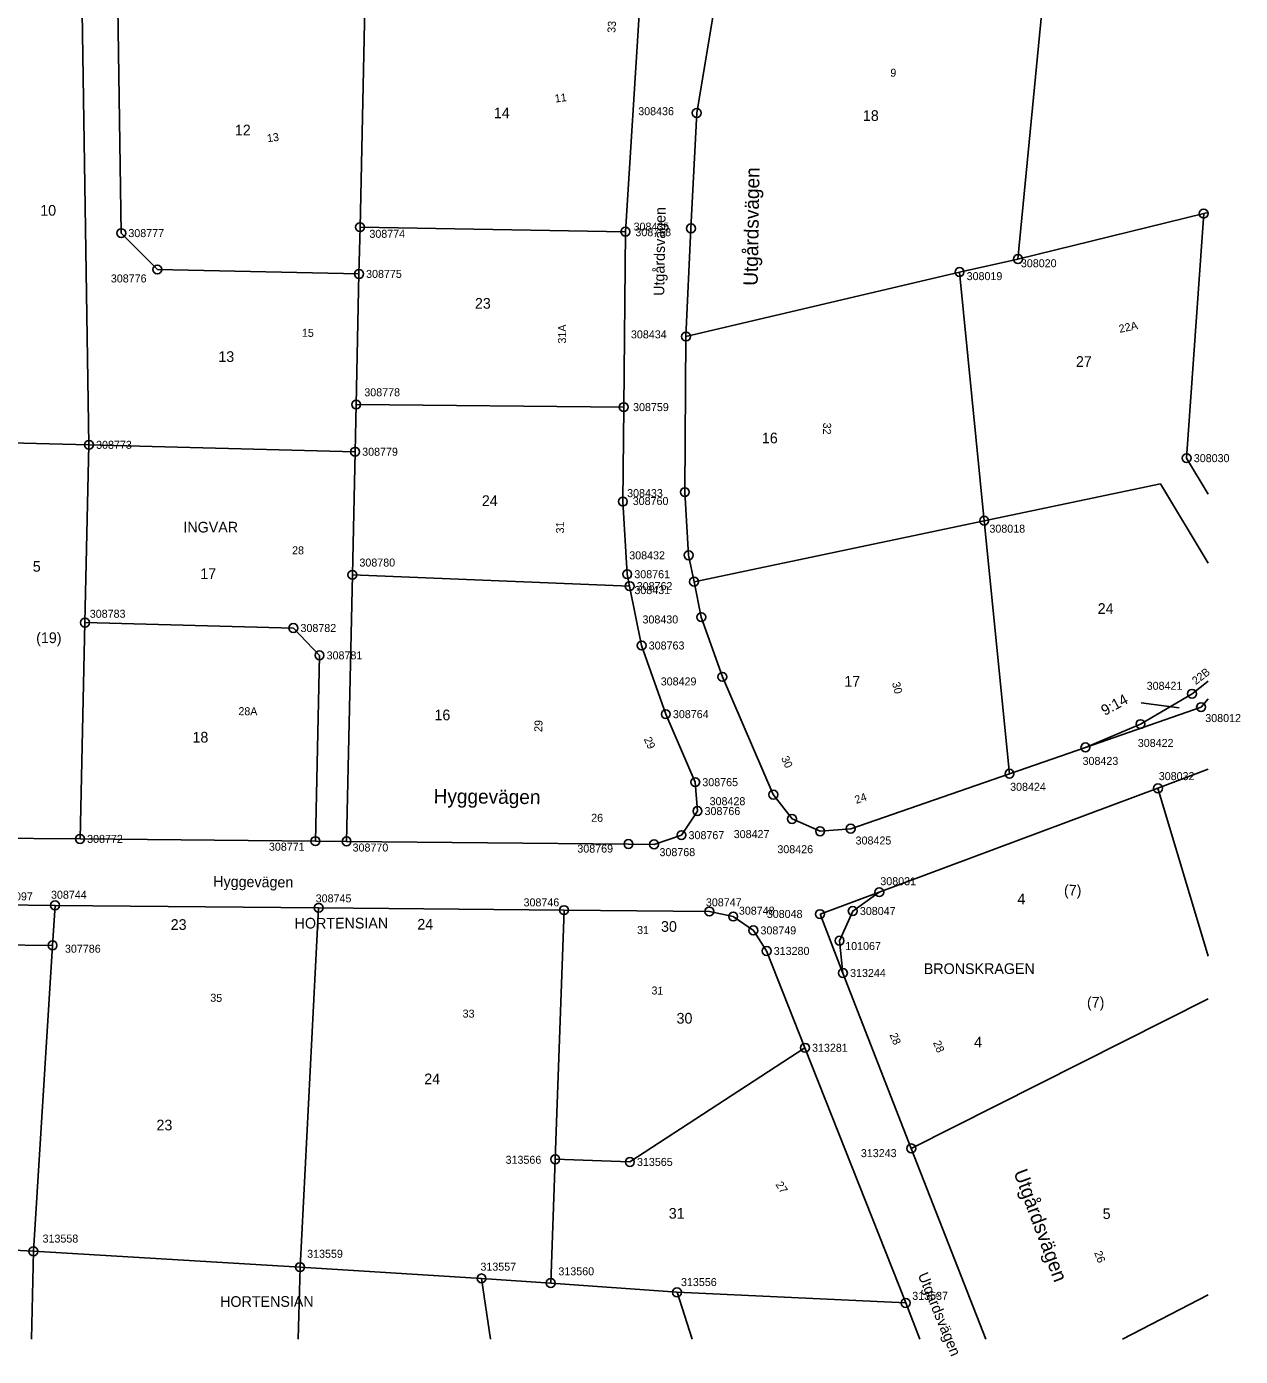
# Model space of a CAD drawing. Extents: x 141995 to 152570, y 6580184 to 6586000.
# Drawn here: x 142867.1 to 143003.6, y 6584998.1 to 6585147.6 of the extents above; entities that cross this region are included whole.
import ezdxf

# ---------------------------------------------------------------- set-up
doc = ezdxf.new("R2010")
doc.units = 0
for name, color, linetype in [('Level 10', 7, 'Continuous'), ('Level 40', 7, 'Continuous'), ('Level 42', 7, 'Continuous'), ('Level 43', 7, 'Continuous'), ('Level 5', 7, 'Continuous'), ('Level 50', 7, 'Continuous'), ('Level 51', 7, 'Continuous'), ('Level 52', 7, 'Continuous'), ('Level 53', 7, 'Continuous'), ('Level 54', 7, 'Continuous'), ('Level 55', 7, 'Continuous'), ('Level 58', 7, 'Continuous'), ('Level 59', 7, 'Continuous'), ('Level 6', 7, 'Continuous'), ('Level 60', 7, 'Continuous'), ('Level 7', 7, 'Continuous')]:
    doc.layers.add(name, color=color, linetype=linetype)

msp = doc.modelspace()

# ---------------------------------------------------------------- linework, layer by layer
at = {"layer": 'Level 10'}
for centre in [(142942.47, 6585137.91), (142999.49, 6585126.6), (142877.74, 6585124.4), (142904.6, 6585125.07), (142934.45, 6585124.56), (142941.82, 6585124.93), (142978.6, 6585121.48), (142881.8, 6585120.31), (142904.48, 6585119.81), (142972.03, 6585120.02), (142941.26, 6585112.77), (142904.16, 6585105.12), (142934.26, 6585104.83), (142874.11, 6585100.59), (142904.04, 6585099.81), (142997.57, 6585099.09), (142934.16, 6585094.21), (142941.13, 6585095.27), (142974.8, 6585092.06), (142941.56, 6585088.17), (142903.74, 6585085.97), (142934.65, 6585086.04), (142942.17, 6585085.2), (142934.92, 6585084.7), (142873.66, 6585080.59), (142942.98, 6585081.21), (142897.1, 6585079.98), (142936.27, 6585078.02), (142900.04, 6585076.91), (142945.35, 6585074.5), (142998.18, 6585072.59), (142938.99, 6585070.3), (142999.2, 6585071.09), (142992.38, 6585069.18), (142986.19, 6585066.56), (142942.3, 6585062.65), (142977.65, 6585063.6), (142951.08, 6585061.25), (142994.35, 6585061.96), (142942.55, 6585059.4), (142953.19, 6585058.52), (142940.75, 6585056.69), (142956.35, 6585057.13), (142959.79, 6585057.42), (142873.1, 6585056.27), (142899.58, 6585056.02), (142903.08, 6585055.99), (142934.79, 6585055.69), (142937.67, 6585055.66), (142963, 6585050.28), (142870.29, 6585048.8), (142899.94, 6585048.52), (142927.54, 6585048.26), (142943.89, 6585048.11), (142956.34, 6585047.81), (142960.02, 6585048.16), (142946.57, 6585047.54), (142948.84, 6585045.98), (142958.53, 6585044.82), (142870.01, 6585044.3), (142950.33, 6585043.67), (142958.91, 6585041.19), (142954.64, 6585032.78), (142966.6, 6585021.46), (142926.55, 6585020.24), (142934.95, 6585019.94), (142867.86, 6585009.89), (142897.85, 6585008.11), (142918.26, 6585006.84), (142926.05, 6585006.32), (142940.25, 6585005.28), (142965.97, 6585004.08)]:
    msp.add_circle(centre, 0.5, dxfattribs=at)
at = {"layer": 'Level 5'}
for points in [[(142942.47, 6585137.91), (142945.38, 6585155.26)], [(142936.08, 6585150.19), (142934.45, 6585124.56)], [(142941.82, 6585124.93), (142942.47, 6585137.91)], [(142934.45, 6585124.56), (142934.26, 6585104.83)], [(142941.26, 6585112.77), (142941.82, 6585124.93)], [(142941.13, 6585095.27), (142941.26, 6585112.77)], [(142934.26, 6585104.83), (142934.16, 6585094.21)], [(142941.56, 6585088.17), (142941.13, 6585095.27)], [(142934.16, 6585094.21), (142934.65, 6585086.04)], [(142942.17, 6585085.2), (142941.56, 6585088.17)], [(142934.65, 6585086.04), (142934.92, 6585084.7)], [(142934.92, 6585084.7), (142936.27, 6585078.02)], [(142942.98, 6585081.21), (142942.17, 6585085.2)], [(142945.35, 6585074.5), (142942.98, 6585081.21)], [(142936.27, 6585078.02), (142938.99, 6585070.3)], [(142951.08, 6585061.25), (142945.35, 6585074.5)], [(143000, 6585074.01), (142998.18, 6585072.59)], [(142998.18, 6585072.59), (142992.38, 6585069.18)], [(142938.99, 6585070.3), (142942.3, 6585062.65)], [(142992.38, 6585069.18), (142986.19, 6585066.56)], [(142986.19, 6585066.56), (142977.65, 6585063.6)], [(142977.65, 6585063.6), (142959.79, 6585057.42)], [(142994.35, 6585061.96), (143000, 6585064.1)], [(142942.3, 6585062.65), (142942.55, 6585059.4)], [(142963, 6585050.28), (142994.35, 6585061.96)], [(142953.19, 6585058.52), (142951.08, 6585061.25)], [(142942.55, 6585059.4), (142940.75, 6585056.69)], [(142956.35, 6585057.13), (142953.19, 6585058.52)], [(142959.79, 6585057.42), (142956.35, 6585057.13)], [(142862.62, 6585056.37), (142873.1, 6585056.27)], [(142899.58, 6585056.02), (142873.1, 6585056.27)], [(142903.08, 6585055.99), (142899.58, 6585056.02)], [(142934.79, 6585055.69), (142903.08, 6585055.99)], [(142937.67, 6585055.66), (142934.79, 6585055.69)], [(142940.75, 6585056.69), (142937.67, 6585055.66)], [(142956.34, 6585047.81), (142963, 6585050.28)], [(142870.29, 6585048.8), (142870.01, 6585044.3)], [(142870.29, 6585048.8), (142899.94, 6585048.52)], [(142899.94, 6585048.52), (142927.54, 6585048.26)], [(142927.54, 6585048.26), (142943.89, 6585048.11)], [(142943.89, 6585048.11), (142946.57, 6585047.54)], [(142946.57, 6585047.54), (142948.84, 6585045.98)], [(142956.34, 6585047.81), (142958.91, 6585041.19)], [(142948.84, 6585045.98), (142950.33, 6585043.67)], [(142857.61, 6585044.43), (142870.01, 6585044.3)], [(142950.33, 6585043.67), (142954.64, 6585032.78)], [(142966.6, 6585021.46), (142958.91, 6585041.19)], [(142954.64, 6585032.78), (142965.97, 6585004.08)], [(142974.97, 6585000), (142966.6, 6585021.46)], [(142965.97, 6585004.08), (142967.58, 6585000)]]:
    msp.add_lwpolyline(points, dxfattribs=at)
at = {"layer": 'Level 51'}
msp.add_lwpolyline([(142992.44, 6585071.56), (142996.73, 6585071.01)], dxfattribs=at)
at = {"layer": 'Level 6'}
for points in [[(143000, 6585165.66), (142982.69, 6585163.68), (142949.66, 6585159.38), (142948.14, 6585158.93), (142946.84, 6585158.03), (142945.88, 6585156.76), (142945.38, 6585155.26), (142942.47, 6585137.91), (142941.82, 6585124.93), (142941.26, 6585112.77), (142941.13, 6585095.27), (142941.56, 6585088.17), (142942.17, 6585085.2), (142942.98, 6585081.21), (142945.35, 6585074.5), (142951.08, 6585061.25), (142953.19, 6585058.52), (142956.35, 6585057.13), (142959.79, 6585057.42), (142977.65, 6585063.6), (142986.19, 6585066.56), (142992.38, 6585069.18), (142998.18, 6585072.59), (143000, 6585074.01)], [(142862.62, 6585056.37), (142873.1, 6585056.27), (142899.58, 6585056.02), (142903.08, 6585055.99), (142934.79, 6585055.69), (142937.67, 6585055.66), (142940.75, 6585056.69), (142942.55, 6585059.4), (142942.3, 6585062.65), (142938.99, 6585070.3), (142936.27, 6585078.02), (142934.92, 6585084.7), (142934.65, 6585086.04), (142934.16, 6585094.21), (142934.26, 6585104.83), (142934.45, 6585124.56), (142936.08, 6585150.19)], [(143000, 6585064.1), (142994.35, 6585061.96), (142963, 6585050.28), (142960.02, 6585048.16), (142958.53, 6585044.82), (142958.91, 6585041.19), (142966.6, 6585021.46), (142974.97, 6585000)], [(142967.58, 6585000), (142965.97, 6585004.08), (142954.64, 6585032.78), (142950.33, 6585043.67), (142948.84, 6585045.98), (142946.57, 6585047.54), (142943.89, 6585048.11), (142927.54, 6585048.26), (142899.94, 6585048.52), (142870.29, 6585048.8), (142864.27, 6585048.86)]]:
    msp.add_lwpolyline(points, dxfattribs=at)
at = {"layer": 'Level 7'}
for points in [[(142982.69, 6585163.68), (142978.6, 6585121.48)], [(142905.22, 6585153.39), (142904.6, 6585125.07)], [(142877.74, 6585124.4), (142877.35, 6585149.77)], [(142873.36, 6585149.26), (142874.11, 6585100.59)], [(142978.6, 6585121.48), (142999.49, 6585126.6)], [(142999.49, 6585126.6), (142997.57, 6585099.09)], [(143000, 6585126.72), (142999.49, 6585126.6)], [(142881.8, 6585120.31), (142877.74, 6585124.4)], [(142904.6, 6585125.07), (142904.48, 6585119.81)], [(142934.45, 6585124.56), (142904.6, 6585125.07)], [(142972.03, 6585120.02), (142978.6, 6585121.48)], [(142904.48, 6585119.81), (142881.8, 6585120.31)], [(142941.26, 6585112.77), (142972.03, 6585120.02)], [(142974.8, 6585092.06), (142972.03, 6585120.02)], [(142904.48, 6585119.81), (142904.16, 6585105.12)], [(142904.16, 6585105.12), (142904.04, 6585099.81)], [(142934.26, 6585104.83), (142904.16, 6585105.12)], [(142849.02, 6585101.23), (142874.11, 6585100.59)], [(142873.66, 6585080.59), (142874.11, 6585100.59)], [(142904.04, 6585099.81), (142874.11, 6585100.59)], [(142903.74, 6585085.97), (142904.04, 6585099.81)], [(142997.57, 6585099.09), (143000, 6585095.04)], [(142994.63, 6585096.22), (142974.8, 6585092.06)], [(143000, 6585087.27), (142994.63, 6585096.22)], [(142942.17, 6585085.2), (142974.8, 6585092.06)], [(142977.65, 6585063.6), (142974.8, 6585092.06)], [(142903.08, 6585055.99), (142903.74, 6585085.97)], [(142934.92, 6585084.7), (142903.74, 6585085.97)], [(142873.1, 6585056.27), (142873.66, 6585080.59)], [(142897.1, 6585079.98), (142873.66, 6585080.59)], [(142900.04, 6585076.91), (142897.1, 6585079.98)], [(142899.58, 6585056.02), (142900.04, 6585076.91)], [(143000, 6585072.02), (142999.2, 6585071.09)], [(142999.2, 6585071.09), (142986.19, 6585066.56)], [(142994.35, 6585061.96), (143000, 6585043.09)], [(142899.94, 6585048.52), (142897.85, 6585008.11)], [(142927.54, 6585048.26), (142926.55, 6585020.24)], [(142867.86, 6585009.89), (142870.01, 6585044.3)], [(143000, 6585038.3), (142966.6, 6585021.46)], [(142954.64, 6585032.78), (142934.95, 6585019.94)], [(142926.55, 6585020.24), (142926.05, 6585006.32)], [(142934.95, 6585019.94), (142926.55, 6585020.24)], [(142834.61, 6585011.58), (142867.86, 6585009.89)], [(142867.63, 6585000), (142867.86, 6585009.89)], [(142897.85, 6585008.11), (142867.86, 6585009.89)], [(142897.85, 6585008.11), (142897.63, 6585000)], [(142918.26, 6585006.84), (142897.85, 6585008.11)], [(142919.28, 6585000), (142918.26, 6585006.84)], [(142918.26, 6585006.84), (142926.05, 6585006.32)], [(142926.05, 6585006.32), (142940.25, 6585005.28)], [(142940.25, 6585005.28), (142965.97, 6585004.08)], [(142941.96, 6585000), (142940.25, 6585005.28)], [(143000, 6585005.01), (142990.36, 6585000)]]:
    msp.add_lwpolyline(points, dxfattribs=at)

# ---------------------------------------------------------------- texts
at = {"layer": 'Level 40'}
msp.add_text('Utgårdsvägen', height=1.2, rotation=89.0539, dxfattribs=at).set_placement((142938.81, 6585117.34))
at = {"layer": 'Level 42'}
for s, rotation, p in [('Hyggevägen', 359.4524, (142888.08, 6585050.89)), ('Utgårdsvägen', 292.3139, (142967.32, 6585007.22))]:
    msp.add_text(s, height=1.2, rotation=rotation, dxfattribs=at).set_placement(p)
at = {"layer": 'Level 43'}
for s, rotation, p in [('Utgårdsvägen', 89.0539, (142949.32, 6585118.47)), ('Hyggevägen', 359.4524, (142912.87, 6585060.29)), ('Utgårdsvägen', 290.3839, (142978.08, 6585018.78))]:
    msp.add_text(s, height=1.6, rotation=rotation, dxfattribs=at).set_placement(p)
at = {"layer": 'Level 50'}
for s, p in [('BRONSKRAGEN', (142968.01, 6585041.07)), ('HORTENSIAN', (142888.86, 6585003.64))]:
    msp.add_text(s, height=1.2, rotation=0.0514, dxfattribs=at).set_placement(p)
at = {"layer": 'Level 51'}
for s, rotation, p in [('14', 0.0514, (142919.65, 6585137.32)), ('18', 0.0514, (142961.16, 6585137.02)), ('12', 0.0514, (142890.52, 6585135.39)), ('13', 0.0514, (142888.66, 6585109.91)), ('27', 0.0514, (142985.12, 6585109.36)), ('16', 0.0514, (142949.8, 6585100.76)), ('24', 0.0514, (142918.3, 6585093.71)), ('17', 0.0514, (142886.63, 6585085.5)), ('24', 0.0514, (142987.57, 6585081.58)), ('17', 0.0514, (142959.07, 6585073.39)), ('9:14', 28.6183, (142988.36, 6585070.09)), ('16', 0.0514, (142912.97, 6585069.61)), ('18', 0.0514, (142885.75, 6585067.11)), ('30', 0.0514, (142940.2, 6585035.5)), ('4', 359.1063, (142973.66, 6585032.83)), ('24', 0.0514, (142911.82, 6585028.68)), ('23', 0.0514, (142881.7, 6585023.49)), ('31', 0.0514, (142939.32, 6585013.56)), ('5', 0.0514, (142988.13, 6585013.52))]:
    msp.add_text(s, height=1.2, rotation=rotation, dxfattribs=at).set_placement(p)
msp.add_text('23', height=1.2, dxfattribs=at).set_placement((142917.52, 6585115.9))
at = {"layer": 'Level 52'}
msp.add_text('(7)', height=1.2, rotation=359.1063, dxfattribs=at).set_placement((142983.77, 6585049.92))
at = {"layer": 'Level 53'}
for s, p in [('308436', (142935.89, 6585137.66)), ('308777', (142878.54, 6585123.95)), ('308774', (142905.65, 6585123.87)), ('308435', (142935.37, 6585124.68)), ('308758', (142935.57, 6585124.05)), ('308020', (142978.93, 6585120.56)), ('308775', (142905.28, 6585119.36)), ('308019', (142972.83, 6585119.11)), ('308776', (142876.57, 6585118.85)), ('308434', (142935.07, 6585112.56)), ('308778', (142905.08, 6585106.05)), ('308759', (142935.31, 6585104.38)), ('308773', (142874.91, 6585100.14)), ('308779', (142904.84, 6585099.36)), ('308030', (142998.38, 6585098.64)), ('308433', (142934.64, 6585094.71)), ('308760', (142935.27, 6585093.82)), ('308018', (142975.39, 6585090.71)), ('308432', (142934.88, 6585087.71)), ('308780', (142904.53, 6585086.9)), ('308761', (142935.45, 6585085.59)), ('308431', (142935.46, 6585083.8)), ('308762', (142935.72, 6585084.25)), ('308783', (142874.2, 6585081.14)), ('308430', (142936.37, 6585080.5)), ('308782', (142897.9, 6585079.54)), ('308763', (142937.07, 6585077.57)), ('308781', (142900.84, 6585076.46)), ('308429', (142938.42, 6585073.53)), ('308421', (142993.08, 6585073.04)), ('308764', (142939.79, 6585069.85)), ('308012', (142999.67, 6585069.41)), ('308422', (142992.08, 6585066.61)), ('308423', (142985.87, 6585064.59)), ('308765', (142943.1, 6585062.2)), ('308032', (142994.44, 6585062.88)), ('308424', (142977.72, 6585061.68)), ('308428', (142943.92, 6585060.06)), ('308766', (142943.35, 6585058.95)), ('308767', (142941.55, 6585056.24)), ('308427', (142946.63, 6585056.36)), ('308772', (142873.9, 6585055.82)), ('308771', (142894.35, 6585054.94)), ('308770', (142903.76, 6585054.85)), ('308769', (142929.04, 6585054.73)), ('308426', (142951.54, 6585054.66)), ('308425', (142960.34, 6585055.64)), ('308768', (142938.28, 6585054.33)), ('308031', (142963.12, 6585051.06)), ('313097', (142863.78, 6585049.36)), ('308744', (142869.84, 6585049.54)), ('308745', (142899.61, 6585049.13)), ('308746', (142922.99, 6585048.68)), ('308747', (142943.5, 6585048.69)), ('308748', (142947.21, 6585047.75)), ('308048', (142950.35, 6585047.38)), ('308047', (142960.82, 6585047.71)), ('308749', (142949.64, 6585045.53)), ('307786', (142871.41, 6585043.47)), ('313280', (142951.13, 6585043.22)), ('101067', (142959.17, 6585043.77)), ('313244', (142959.72, 6585040.74)), ('313281', (142955.44, 6585032.33)), ('313243', (142960.93, 6585020.48)), ('313566', (142920.97, 6585019.73)), ('313565', (142935.75, 6585019.49)), ('313558', (142868.89, 6585010.87)), ('313559', (142898.65, 6585009.16)), ('313557', (142918.14, 6585007.71)), ('313560', (142926.91, 6585007.19)), ('313556', (142940.7, 6585005.98)), ('313537', (142966.71, 6585004.43))]:
    msp.add_text(s, height=0.9, rotation=0.0514, dxfattribs=at).set_placement(p)
at = {"layer": 'Level 54'}
for s, rotation, p in [('9', 356.4573, (142964.22, 6585142.01)), ('11', 7.4014, (142926.56, 6585139.08)), ('13', 7.4114, (142894.19, 6585134.62)), ('31A', 89.4459, (142927.76, 6585111.98)), ('22A', 11.7821, (142990.05, 6585113.18)), ('15', 358.9283, (142898.05, 6585112.75)), ('32', 269.4249, (142956.69, 6585103.09)), ('31', 89.4459, (142927.54, 6585090.62)), ('28', 359.4624, (142896.95, 6585088.28)), ('22B', 37.9791, (142998.61, 6585073.56)), ('30', 283.7588, (142964.43, 6585073.81)), ('28A', 359.4153, (142890.91, 6585070.19)), ('29', 87.4959, (142925.08, 6585068.28)), ('31', 357.6133, (142937.36, 6585038.79)), ('35', 357.9653, (142887.74, 6585037.97)), ('33', 359.2553, (142916.13, 6585036.18)), ('28', 292.4589, (142969.03, 6585033.37)), ('27', 303.17, (142951.29, 6585017.4)), ('26', 290.3839, (142987.16, 6585009.75))]:
    msp.add_text(s, height=0.9, rotation=rotation, dxfattribs=at).set_placement(p)
at = {"layer": 'Level 55'}
for s, rotation, p in [('33', 86.325, (142933.31, 6585146.9)), ('29', 294.0619, (142936.5, 6585067.5)), ('30', 294.1399, (142951.94, 6585065.36)), ('24', 19.4064, (142960.42, 6585060.2)), ('26', 359.5564, (142930.59, 6585058.2)), ('31', 359.4733, (142935.76, 6585045.58)), ('28', 292.4589, (142964.14, 6585034.25))]:
    msp.add_text(s, height=0.9, rotation=rotation, dxfattribs=at).set_placement(p)
at = {"layer": 'Level 58'}
for s, p in [('INGVAR', (142884.73, 6585090.73)), ('HORTENSIAN', (142897.24, 6585046.19))]:
    msp.add_text(s, height=1.2, rotation=0.0514, dxfattribs=at).set_placement(p)
at = {"layer": 'Level 59'}
for s, p in [('10', (142868.63, 6585126.36)), ('5', (142867.79, 6585086.32)), ('4', (142978.54, 6585048.92)), ('23', (142883.3, 6585046.04)), ('24', (142911.04, 6585046.07)), ('30', (142938.45, 6585045.82))]:
    msp.add_text(s, height=1.2, rotation=0.0514, dxfattribs=at).set_placement(p)
at = {"layer": 'Level 60'}
for s, p in [('(19)', (142868.17, 6585078.29)), ('(7)', (142986.36, 6585037.3))]:
    msp.add_text(s, height=1.2, rotation=0.0514, dxfattribs=at).set_placement(p)

doc.saveas('drawing.dxf')
